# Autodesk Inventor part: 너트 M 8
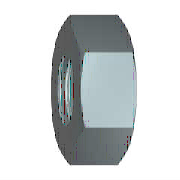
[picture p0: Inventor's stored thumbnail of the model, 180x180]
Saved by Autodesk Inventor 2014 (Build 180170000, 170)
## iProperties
IsCustomPart: 1
Created: 2012-02
Part Number: 너트 M 8
Material: 강철, 연강
Description: 6각 너트 및 6각 가는 너트
Document SubType Name: Modeling
Standard: KS B 1012
Designer: mduedu
Standards Organization: KS
Language: ko-KR
Size Designation: M 8
Categories: <MemberInstance><Categories><Category DisplayName="조임쇠" InternalName="e4da775c-781d-43d5-af7c-5136215cf5a6" Mnemonic="FSTN"><Category DisplayName="너트" InternalN
Density: 1 g/cm^3
Appearance: 강철
Author: mduedu
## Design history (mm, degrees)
sketch "스케치1"
  geometry: L1 (-7.506, 0)-(-3.753, 6.5); L2 (-3.753, 6.5)-(3.753, 6.5); L3 (3.753, 6.5)-(7.506, 0); L4 (7.506, 0)-(3.753, -6.5); L5 (3.753, -6.5)-(-3.753, -6.5); L6 (-3.753, -6.5)-(-7.506, 0); 2 further points
  constraints: 12 end point, 1 coincident, 1 horizontal, 11 other
  dimensions: "d0" = 15.01111 distance of L3.end L1.start (= 1.1547 x SW)
extrude "본체" new body sketch "스케치1" distance "d1" = 5 (= KOH); taper "d2" = 0 deg
sketch "스케치2"
  geometry: L1 (0, 3.753)-(0, 7.506) reference; L2 (0, 7.506)-(5, 7.506) reference; L3 (5, 3.753)-(5, 7.506) reference; L4 (-1, 0)-(6, 0) reference; L5 (0.581, 7.506)-(0, 6.5); L6 (4.419, 7.506)-(5, 6.5)
  constraints: 4 end point, 4 point on line
  dimensions: "d3" = 30 deg angle of L1 L5 (= ANG1); "d4" = 30 deg angle of L3 L6 (= ANG2); "d5" = 13 diameter of L5.end L4 (= SW0); "d6" = 13 diameter of L6.end L4 (= SW01)
revolve "모따기1" sketch "스케치2" stored, may be unused: angle "d7" = 90 deg
sketch "스케치3"
  geometry: A1 r 6.5 centre (0, 0) between (-3.25, -5.629) and (3.25, -5.629) reference; 1 further point
  constraints: 1 coincident
hole "스레드" sketch "스케치3" at (0, 0) diameter "d25" = 6.647; stored, may be unused: countersink angle "d29" = 82 deg, drill point angle "d31" = 118 deg; dims "d26" = 6, "d27" = 4, "d28" = 2, "d30" = 8
workaxis "Work Axis1"
workplane "Work Plane1"
body "Solid1"
chamfer "모따기2" distance "d8" = 0.67658 (= -0.5 x GD1 + 0.5 x NND); stored, may be unused: angle "d9" = 30 deg, second distance "d40" = 0.67658 (= -0.5 x GD1 + 0.5 x NND)
chamfer "모따기3" distance "d10" = 0.67658 (= -0.5 x GD1 + 0.5 x NND); stored, may be unused: angle "d11" = 30 deg, second distance "d41" = 0.67658 (= -0.5 x GD1 + 0.5 x NND)
other parameters: "ANG1" = 30 deg [user parameter; used in 1 equation term], "ANG2" = 30 deg [user parameter; used in 1 equation term], "NND" = 8 [user parameter; used in 4 equation terms], "KOH" = 5 [user parameter; used in 1 equation term], "SW" = 13 [user parameter; used in 4 equation terms], "SW0" = 13 (= SW) [user parameter; used in 1 equation term], "SW01" = 13 (= SW) [user parameter; used in 1 equation term], "GD1" = 6.64684 (computed from THREADDIA, PTC, TOA) [user parameter; used in 4 equation terms], "d13" = 0, "d14" = 0, "d39" = 0, "d42" = 0, "GUL" = 0.67658 (= 0.541266 x PTC) [user parameter], "TPU" = 8 (computed from PTC) [user parameter], "THREADDIA" = 8 [user parameter; used in 1 equation term], "TOA" = 30 deg [user parameter; used in 1 equation term], "PTC" = 1.25 [user parameter; used in 4 equation terms], "E0" = 15.015 (= 1.155 x SW) [user parameter], "GAL" = 0.67658 (= 0.541266 x PTC) [user parameter]
